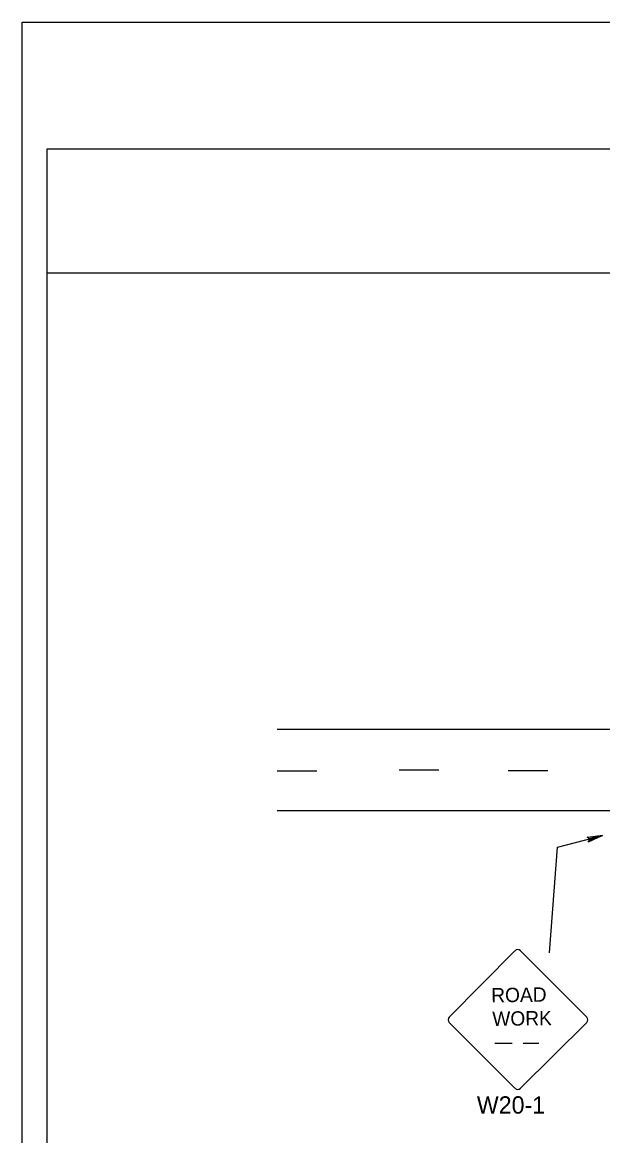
# Model space of a CAD drawing. Extents: x -14145 to -13521, y 30244 to 30661.
# Drawn here: x -13824.17 to -13817.15, y 30517.84 to 30531.31 of the extents above; entities that cross this region are included whole.
import ezdxf

# ---------------------------------------------------------------- set-up
doc = ezdxf.new("R2010")
doc.units = 0
for name, color, linetype in [('1', 7, 'Continuous'), ('10', 7, 'Continuous'), ('2', 7, 'Continuous'), ('61', 7, 'Continuous')]:
    doc.layers.add(name, color=color, linetype=linetype)

msp = doc.modelspace()

# ---------------------------------------------------------------- linework, layer by layer
at = {"layer": '1'}
for p, q in [((-13821.088, 30522.756), (-13794.808, 30522.756)), ((-13820.608, 30522.246), (-13821.088, 30522.246)), ((-13819.132, 30522.258), (-13819.612, 30522.258)), ((-13817.812, 30522.252), (-13818.292, 30522.252)), ((-13821.088, 30521.772), (-13794.808, 30521.772)), ((-13817.696, 30521.326), (-13817.149, 30521.466)), ((-13817.79, 30520.05), (-13817.696, 30521.326)), ((-13818.209, 30520.074), (-13819.004, 30519.271)), ((-13817.34, 30519.271), (-13818.143, 30520.074)), ((-13819.004, 30519.205), (-13818.209, 30518.41)), ((-13818.143, 30518.41), (-13817.34, 30519.205)), ((-13818.455, 30518.957), (-13818.245, 30518.957)), ((-13818.112, 30518.957), (-13817.919, 30518.957))]:
    msp.add_line(p, q, dxfattribs=at)
msp.add_lwpolyline([(-13817.329, 30521.442), (-13817.317, 30521.43), (-13817.149, 30521.466), (-13817.329, 30521.442), (-13817.335, 30521.448), (-13817.149, 30521.466), (-13817.311, 30521.412), (-13817.317, 30521.4), (-13817.149, 30521.466), (-13817.323, 30521.388), (-13817.317, 30521.4)], dxfattribs=at)
for centre, start, end in [((-13818.176, 30520.041), 45, 135), ((-13818.971, 30519.239), 135, 225), ((-13817.373, 30519.238), 315, 45), ((-13818.176, 30518.443), 225, 315)]:
    msp.add_arc(centre, 0.0465, start, end, dxfattribs=at)
at = {"layer": '10'}
for p, q in [((-13823.874, 30529.777), (-13792.422, 30529.777)), ((-13823.874, 30507.207), (-13823.874, 30529.777)), ((-13823.874, 30528.277), (-13792.422, 30528.277))]:
    msp.add_line(p, q, dxfattribs=at)
at = {"layer": '61'}
msp.add_lwpolyline([(-13824.174, 30531.307), (-13791.174, 30531.307), (-13791.174, 30505.807), (-13824.174, 30505.807)], close=True, dxfattribs=at)

# ---------------------------------------------------------------- texts
at = {"layer": '1'}
for s, height, rotation, p in [('ROAD', 0.1735, 0.7566, (-13818.496, 30519.449)), ('WORK', 0.1733, 0.7588, (-13818.483, 30519.164))]:
    msp.add_text(s, height=height, rotation=rotation, dxfattribs=at).set_placement(p)
at = {"layer": '2'}
msp.add_text('W20-1', height=0.21, dxfattribs=at).set_placement((-13818.671, 30518.103))

doc.saveas('drawing.dxf')
